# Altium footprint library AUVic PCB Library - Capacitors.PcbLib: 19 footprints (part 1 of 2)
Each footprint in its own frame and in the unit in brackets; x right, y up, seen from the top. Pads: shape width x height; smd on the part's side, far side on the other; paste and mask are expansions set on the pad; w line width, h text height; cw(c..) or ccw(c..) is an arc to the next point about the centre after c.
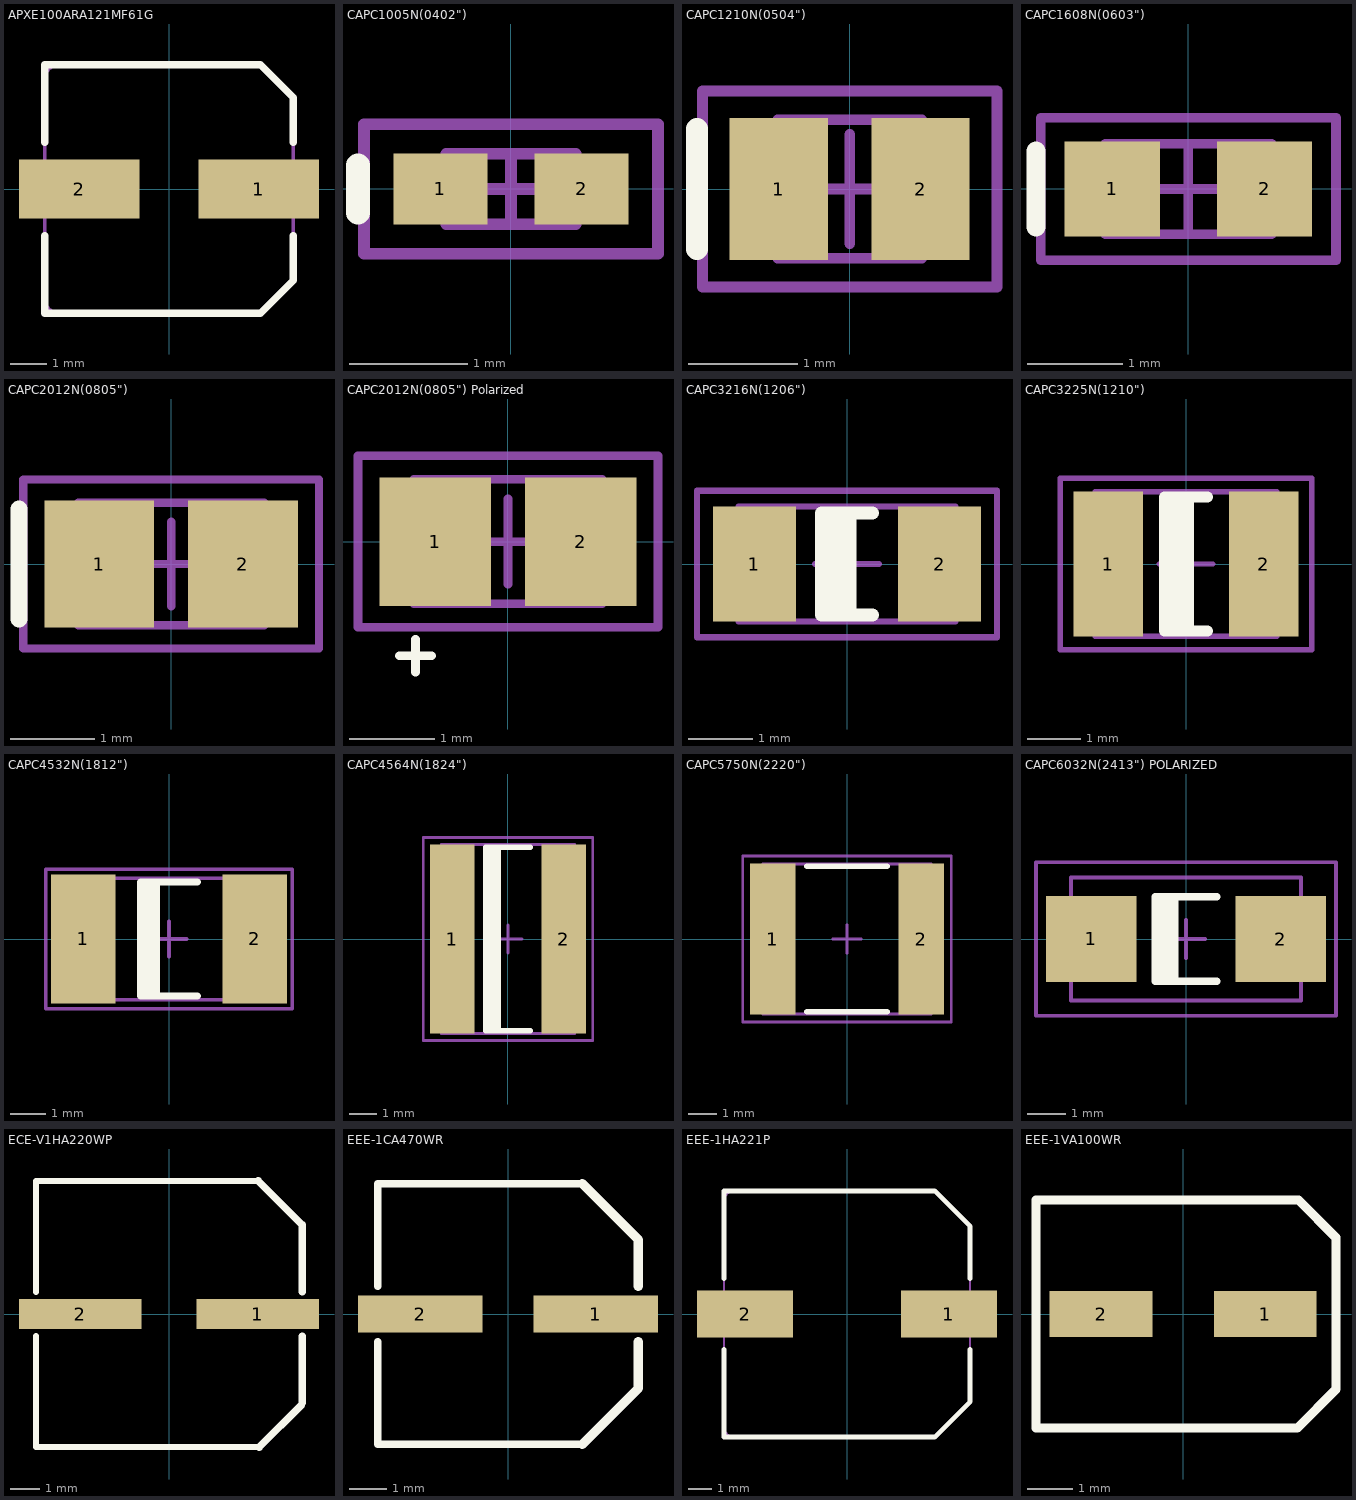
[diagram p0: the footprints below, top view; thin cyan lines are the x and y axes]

## APXE100ARA121MF61G [mm] "Capacitor, SMD, Digi#565-3200-1-ND, United Chemi-Con"
height 5.8
pads (2):
  rect 3.3x1.6 smd: 1(2.45,0) 2(-2.45,0)
Top Overlay:
  lines w0.2: -3.4,-1.27 -3.4,-3.4 2.5,-3.4 3.4,-2.5 3.4,-1.27 ; -3.4,1.27 -3.4,3.4 2.5,3.4 3.4,2.5 3.4,1.27
Mechanical 13:
  lines w0.1: -3.4,-3 ccw(c-3,-3) -3,-3.4 2.5,-3.4 3.4,-2.5 3.4,2.5 2.5,3.4 -3,3.4 ccw(c-3,3) -3.4,3 -3.4,-3
3D body: height 0.5, standoff 0, extent -3.408,-3.408 3.401,3.408
3D body: height 6.1, standoff 0.05, extent -3.373,-3.393 3.4,3.393

## CAPC1005N(0402") [mm] "Chip Capacitor, Body 1.0x0.5mm (0402\"), IPC Medium Density"
height 0.6
pads (2):
  rect 0.8x0.6 smd: 1(-0.6,0) 2(0.6,0)
Top Overlay:
  lines w0.2: -1.3,-0.2 -1.3,0.2
Mechanical 13:
  lines w0.1: -0.55,-0.3 -0.55,0.3 0.55,0.3 0.55,-0.3 -0.55,-0.3
Mechanical 15:
  lines w0.1: -0.3,0 0.3,0 ; 0,-0.3 0,0.3 ; -1.25,-0.55 -1.25,0.55 1.25,0.55 1.25,-0.55 -1.25,-0.55
3D body: height 0.6, standoff 0, extent -0.55,-0.3 0.55,0.3

## CAPC1210N(0504") [mm] "Chip Capacitor, Body 1.2x1.0mm (0504\"), IPC Medium Density"
height 1.02
pads (2):
  rect 0.9x1.3 smd: 1(-0.65,0) 2(0.65,0)
Top Overlay:
  lines w0.2: -1.4,-0.55 -1.4,0.55
Mechanical 13:
  lines w0.1: -0.66,-0.635 0.66,-0.635 0.66,0.635 -0.66,0.635 -0.66,-0.635
Mechanical 15:
  lines w0.1: -0.5,0 0.5,0 ; 0,-0.5 0,0.5 ; -1.35,-0.9 1.35,-0.9 1.35,0.9 -1.35,0.9 -1.35,-0.9
3D body: height 1.02, standoff 0, extent -0.66,-0.635 0.66,0.635

## CAPC1608N(0603") [mm] "Chip Capacitor, Body 1.6x0.8mm (0603\"), IPC Medium Density"
height 0.85
pads (2):
  rect 1x1 smd: 1(-0.8,0) 2(0.8,0)
Top Overlay:
  lines w0.2: -1.6,-0.4 -1.6,0.4
Mechanical 13:
  lines w0.1: -0.875,-0.475 0.875,-0.475 0.875,0.475 -0.875,0.475 -0.875,-0.475
Mechanical 15:
  lines w0.1: -0.475,0 0.475,0 ; 0,-0.475 0,0.475 ; -1.55,-0.75 1.55,-0.75 1.55,0.75 -1.55,0.75 -1.55,-0.75
3D body: height 0.85, standoff 0, extent -0.875,-0.475 0.875,0.475

## CAPC2012N(0805") [mm] "Chip Capacitor, Body 2.0x1.3mm (0805\"), IPC Medium Density"
height 1.1
pads (2):
  rect 1.3x1.5 smd: 1(-0.85,0) 2(0.85,0)
Top Overlay:
  lines w0.2: -1.8,-0.65 -1.8,0.65
Mechanical 13:
  lines w0.1: -1.1,-0.725 1.1,-0.725 1.1,0.725 -1.1,0.725 -1.1,-0.725
Mechanical 15:
  lines w0.1: -0.5,0 0.5,0 ; 0,-0.5 0,0.5 ; -1.75,-1 1.75,-1 1.75,1 -1.75,1 -1.75,-1
3D body: height 1.1, standoff 0, extent -1.1,-0.725 1.1,0.725

## CAPC2012N(0805") Polarized [mm] "Chip Capacitor, Polarized, Body 2.0x1.3mm (0805\"), IPC Medium Density"
height 1.1
pads (2):
  rect 1.3x1.5 smd: 1(-0.85,0) 2(0.85,0)
Top Overlay:
  lines w0.1: -1.27,-1.333 -0.889,-1.333 ; -1.079,-1.524 -1.079,-1.143
Mechanical 13:
  lines w0.1: -1.1,-0.725 -1.1,0.725 1.1,0.725 1.1,-0.725 -1.1,-0.725
Mechanical 15:
  lines w0.1: -0.5,0 0.5,0 ; 0,-0.5 0,0.5 ; -1.75,-1 -1.75,1 1.75,1 1.75,-1 -1.75,-1
3D body: height 1.1, standoff 0, extent -1.1,-0.725 1.1,0.725

## CAPC3216N(1206") [mm] "Chip Capacitor, Body 3.2x1.6mm (1206\"), IPC Medium Density"
height 1.35
pads (2):
  rect 1.3x1.8 smd: 1(-1.45,0) 2(1.45,0)
Top Overlay:
  rectangle: -0.4,-0.8 0.15,0.8
  lines w0.2: 0.4,-0.8 -0.4,-0.8 -0.4,0.8 0.4,0.8
Mechanical 13:
  lines w0.1: -1.7,-0.9 -1.7,0.9 1.7,0.9 1.7,-0.9 -1.7,-0.9
Mechanical 15:
  lines w0.1: -0.5,0 0.5,0 ; 0,-0.5 0,0.5 ; -2.35,-1.15 -2.35,1.15 2.35,1.15 2.35,-1.15 -2.35,-1.15
3D body: height 1.35, standoff 0, extent -1.7,-0.9 1.7,0.9

## CAPC3225N(1210") [mm] "Chip Capacitor, Body 3.2x2.5mm (1210\"), IPC Medium Density"
height 1.35
pads (2):
  rect 1.3x2.7 smd: 1(-1.45,0) 2(1.45,0)
Top Overlay:
  rectangle: -0.4,-1.25 0.15,1.25
  lines w0.2: 0.4,-1.25 -0.4,-1.25 -0.4,1.25 0.4,1.25
Mechanical 13:
  lines w0.1: -1.7,-1.35 -1.7,1.35 1.7,1.35 1.7,-1.35 -1.7,-1.35
Mechanical 15:
  lines w0.1: -0.5,0 0.5,0 ; 0,-0.5 0,0.5 ; -2.35,-1.6 -2.35,1.6 2.35,1.6 2.35,-1.6 -2.35,-1.6
3D body: height 1.35, standoff 0, extent -1.7,-1.35 1.7,1.35

## CAPC4532N(1812") [mm] "Chip Capacitor, Body 4.5x3.2mm (1812\"), IPC Medium Density"
height 1.35
pads (2):
  rect 1.8x3.6 smd: 1(-2.4,0) 2(2.4,0)
Top Overlay:
  rectangle: -0.8,-1.6 -0.25,1.6
  lines w0.2: 0.8,-1.6 -0.8,-1.6 -0.8,1.6 0.8,1.6
Mechanical 13:
  lines w0.1: -2.4,-1.7 -2.4,1.7 2.4,1.7 2.4,-1.7 -2.4,-1.7
Mechanical 15:
  lines w0.1: -0.5,0 0.5,0 ; 0,-0.5 0,0.5 ; -3.45,-1.95 -3.45,1.95 3.45,1.95 3.45,-1.95 -3.45,-1.95
3D body: height 1.35, standoff 0, extent -2.4,-1.7 2.4,1.7

## CAPC4564N(1824") [mm] "Chip Capacitor, Body 4.5x6.4mm (1824\"), IPC Medium Density"
height 1.1
pads (2):
  rect 1.6x6.8 smd: 1(-2,0) 2(2,0)
Top Overlay:
  rectangle: -0.8,-3.3 -0.25,3.3
  lines w0.2: 0.8,-3.3 -0.8,-3.3 -0.8,3.3 0.8,3.3
Mechanical 13:
  lines w0.1: -2.4,-3.4 -2.4,3.4 2.4,3.4 2.4,-3.4 -2.4,-3.4
Mechanical 15:
  lines w0.1: -0.5,0 0.5,0 ; 0,-0.5 0,0.5 ; -3.05,-3.65 -3.05,3.65 3.05,3.65 3.05,-3.65 -3.05,-3.65
3D body: height 1.1, standoff 0, extent -2.4,-3.4 2.4,3.4

## CAPC5750N(2220") [mm] "Chip Capacitor, Body 5.7x5.0mm (2220\"), IPC Medium Density"
height 1.35
pads (2):
  rect 1.6x5.3 smd: 1(-2.6,0) 2(2.6,0)
Top Overlay:
  lines w0.2: -1.4,-2.55 1.4,-2.55 ; -1.4,2.55 1.4,2.55
Mechanical 13:
  lines w0.1: -2.95,-2.625 -2.95,2.625 2.95,2.625 2.95,-2.625 -2.95,-2.625
Mechanical 15:
  lines w0.1: -0.5,0 0.5,0 ; 0,-0.5 0,0.5 ; -3.65,-2.9 -3.65,2.9 3.65,2.9 3.65,-2.9 -3.65,-2.9
3D body: height 1.35, standoff 0, extent -2.95,-2.625 2.95,2.625

## CAPC6032N(2413") POLARIZED [mm] "Chip Capacitor, Body 6.0x3.2mm (2413\"), IPC Medium Density"
height 2.5
pads (2):
  rect 2.37x2.23 smd: 1(-2.47,0) 2(2.47,0)
Top Overlay:
  rectangle: -0.8,-1.1 -0.2,1.1
  lines w0.2: 0.8,-1.1 -0.8,-1.1 -0.8,1.1 0.8,1.1
Mechanical 13:
  lines w0.1: -3,-1.6 3,-1.6 3,1.6 -3,1.6 -3,-1.6
Mechanical 15:
  lines w0.1: -0.5,0 0.5,0 ; 0,-0.5 0,0.5 ; -3.91,-2 -3.91,2 3.91,2 3.91,-2 -3.91,-2
3D body: height 1.35, standoff 1.35, extent -2.5,-1.6 -1.7,1.6
3D body: height 1.35, standoff 0, extent -3,-1.6 3,1.6

## ECE-V1HA220WP [mm]
pads (2):
  rect 4.15x1 smd: 1(3,0) 2(-3,0)
Top Overlay:
  lines w0.2: -4.5,-0.75 -4.5,-4.5 3,-4.5 ; -4.5,0.75 -4.5,4.5 3,4.5
  lines w0.254: 3.02,4.5 4.5,3.02 4.5,3 4.5,0.75 ; 3.06,-4.5 4.47,-3.09 ; 4.5,-3 4.5,-0.75

## EEE-1CA470WR [mm]
pads (2):
  rect 3.35x1 smd: 1(2.357,0) 2(-2.357,0)
Top Overlay:
  lines w0.2: -3.5,-0.75 -3.5,-3.5 2,-3.5 ; -3.5,0.75 -3.5,3.5 2,3.5
  lines w0.254: 2,-3.5 3.5,-2 3.5,-0.75 ; 2,3.5 3.5,2 3.5,0.75

## EEE-1HA221P [mm] "Capacitor, SMD, Digi#PCE3921CT-ND, Panasonic-ECG"
height 10.2
pads (2):
  rect 4.1x2 smd: 1(4.35,0) 2(-4.35,0)
Top Overlay:
  lines w0.2: -5.25,-1.5 -5.25,-5.25 3.75,-5.25 5.25,-3.75 5.25,-1.5 ; -5.25,1.5 -5.25,5.25 3.75,5.25 5.25,3.75 5.25,1.5
Mechanical 13:
  lines w0.1: -5.25,-4.85 -5.25,4.827 cw(c-4.827,4.827) -4.827,5.25 3.75,5.25 5.25,3.75 5.25,-3.75 3.75,-5.25 -4.85,-5.25 ; -5.25,-4.827 ccw(c-4.827,-4.827) -4.827,-5.25
3D body: height 0.5, standoff 0, extent -5.259,-5.254 5.251,5.259
3D body: height 11, standoff 0.05, extent -5.209,-5.24 5.25,5.24

## EEE-1VA100WR [mm]
pads (2):
  rect 2.25x1 smd: 1(1.8,0) 2(-1.8,0)
Top Overlay:
  lines w0.2: -3.225,-2.5 -3.225,-0.4 -3.225,2.5 2.525,2.5 3.35,1.675 3.35,-1.65 2.5,-2.5 -3.225,-2.5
